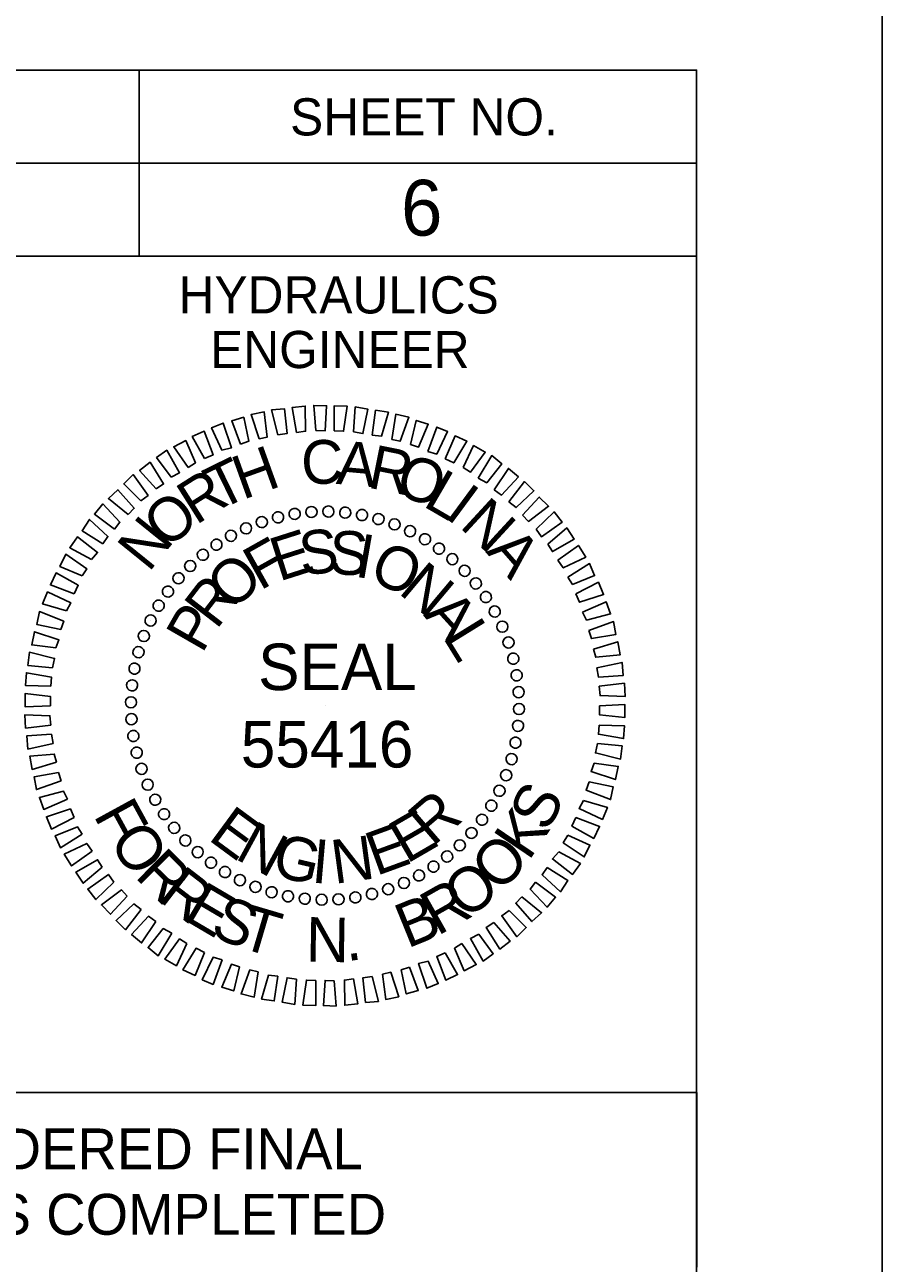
# Model space of a CAD drawing. Extents: x 573078 to 573131.9, y -55221.3 to -55195.5.
# Drawn here: x 573109.706 to 573112.014, y -55203.009 to -55199.677 of the extents above; entities that cross this region are included whole.
import ezdxf

# ---------------------------------------------------------------- set-up
doc = ezdxf.new("R2010")
doc.units = 0
for name, color, linetype in [('Prop Dimension', 7, 'Continuous'), ('Scratch_Level_0', 7, 'Continuous'), ('Scratch_Level_1', 7, 'Continuous'), ('Sheet Data Field CELL', 7, 'Continuous'), ('Sheet Plot Border Inside CELL', 7, 'Continuous'), ('Sheet Profile CELL', 7, 'Continuous'), ('Sheet Sticker Exception Certification CELL', 7, 'Continuous')]:
    doc.layers.add(name, color=color, linetype=linetype)

msp = doc.modelspace()

# ---------------------------------------------------------------- linework, layer by layer
at = {"layer": 'Prop Dimension'}
for p, q in [((573110.3871, -55201.0014), (573110.3871, -55201.0014)), ((573110.4329, -55200.9931), (573110.4329, -55200.9931)), ((573110.4776, -55200.9869), (573110.4776, -55200.9869)), ((573110.5234, -55200.9859), (573110.5234, -55200.9859)), ((573110.5692, -55200.9889), (573110.5692, -55200.9889)), ((573110.6141, -55200.9964), (573110.6141, -55200.9964)), ((573110.6579, -55201.0056), (573110.6579, -55201.0056)), ((573110.3017, -55201.0306), (573110.3017, -55201.0306)), ((573110.3434, -55201.0139), (573110.3434, -55201.0139)), ((573110.7016, -55201.0202), (573110.7016, -55201.0202)), ((573110.7433, -55201.0389), (573110.7433, -55201.0389)), ((573110.2214, -55201.0755), (573110.2214, -55201.0755)), ((573110.261, -55201.0514), (573110.261, -55201.0514)), ((573110.7838, -55201.0598), (573110.7838, -55201.0598)), ((573110.1851, -55201.1014), (573110.1851, -55201.1014)), ((573110.8213, -55201.0859), (573110.8213, -55201.0859)), ((573110.1506, -55201.1327), (573110.1506, -55201.1327)), ((573110.8578, -55201.1139), (573110.8578, -55201.1139)), ((573110.1194, -55201.1651), (573110.1194, -55201.1651)), ((573110.89, -55201.1452), (573110.89, -55201.1452)), ((573110.0914, -55201.2014), (573110.0914, -55201.2014)), ((573110.9212, -55201.1796), (573110.9212, -55201.1796)), ((573110.0652, -55201.2389), (573110.0652, -55201.2389)), ((573110.9474, -55201.216), (573110.9474, -55201.216)), ((573110.9712, -55201.2555), (573110.9712, -55201.2555)), ((573110.0444, -55201.2796), (573110.0444, -55201.2796)), ((573110.992, -55201.2963), (573110.992, -55201.2963)), ((573110.0256, -55201.3213), (573110.0256, -55201.3213)), ((573111.0087, -55201.3379), (573111.0087, -55201.3379)), ((573110.0111, -55201.365), (573110.0111, -55201.365)), ((573110.0018, -55201.4087), (573110.0018, -55201.4087)), ((573111.0212, -55201.3817), (573111.0212, -55201.3817)), ((573111.0295, -55201.4275), (573111.0295, -55201.4275)), ((573109.9944, -55201.4534), (573109.9944, -55201.4534)), ((573111.0358, -55201.4721), (573111.0358, -55201.4721)), ((573109.9914, -55201.4992), (573109.9914, -55201.4992)), ((573111.0369, -55201.518), (573111.0369, -55201.518)), ((573109.9923, -55201.545), (573109.9923, -55201.545)), ((573111.0337, -55201.5638), (573111.0337, -55201.5638)), ((573109.9986, -55201.5899), (573109.9986, -55201.5899)), ((573111.0265, -55201.6087), (573111.0265, -55201.6087)), ((573110.0069, -55201.6358), (573110.0069, -55201.6358)), ((573111.017, -55201.6524), (573111.017, -55201.6524)), ((573110.0194, -55201.6795), (573110.0194, -55201.6795)), ((573111.0025, -55201.6962), (573111.0025, -55201.6962)), ((573110.0361, -55201.7211), (573110.0361, -55201.7211)), ((573110.9837, -55201.7378), (573110.9837, -55201.7378)), ((573110.0569, -55201.7616), (573110.0569, -55201.7616)), ((573110.0809, -55201.8012), (573110.0809, -55201.8012)), ((573110.9629, -55201.7783), (573110.9629, -55201.7783)), ((573110.1069, -55201.8378), (573110.1069, -55201.8378)), ((573110.937, -55201.8158), (573110.937, -55201.8158)), ((573110.1381, -55201.872), (573110.1381, -55201.872)), ((573110.9087, -55201.8524), (573110.9087, -55201.8524)), ((573110.1705, -55201.9033), (573110.1705, -55201.9033)), ((573110.8775, -55201.8845), (573110.8775, -55201.8845)), ((573110.2068, -55201.9315), (573110.2068, -55201.9315)), ((573110.8067, -55201.9419), (573110.8067, -55201.9419)), ((573110.8432, -55201.9158), (573110.8432, -55201.9158)), ((573110.2443, -55201.9574), (573110.2443, -55201.9574)), ((573110.7671, -55201.9658), (573110.7671, -55201.9658)), ((573110.2851, -55201.9783), (573110.2851, -55201.9783)), ((573110.3267, -55201.997), (573110.3267, -55201.997)), ((573110.6849, -55202.0032), (573110.6849, -55202.0032)), ((573110.7266, -55201.9866), (573110.7266, -55201.9866)), ((573110.3705, -55202.0116), (573110.3705, -55202.0116)), ((573110.4142, -55202.0211), (573110.4142, -55202.0211)), ((573110.4589, -55202.0282), (573110.4589, -55202.0282)), ((573110.5047, -55202.0315), (573110.5047, -55202.0315)), ((573110.5505, -55202.0303), (573110.5505, -55202.0303)), ((573110.5954, -55202.0241), (573110.5954, -55202.0241)), ((573110.6412, -55202.0157), (573110.6412, -55202.0157))]:
    msp.add_line(p, q, dxfattribs=at)
for points in [[(573110.3871, -55200.7797), (573110.3705, -55200.7131), (573110.4047, -55200.7099), (573110.4121, -55200.7765)], [(573110.4371, -55200.7735), (573110.4255, -55200.7068), (573110.4609, -55200.7027), (573110.4621, -55200.7703)], [(573110.4892, -55200.7682), (573110.4838, -55200.7006), (573110.5183, -55200.7015), (573110.5142, -55200.7693)], [(573110.5392, -55200.7693), (573110.5392, -55200.7015), (573110.5734, -55200.7027), (573110.5641, -55200.7703)], [(573110.5912, -55200.7723), (573110.5954, -55200.7048), (573110.6296, -55200.711), (573110.6162, -55200.7765)], [(573110.2871, -55200.8047), (573110.2631, -55200.7423), (573110.2955, -55200.7328), (573110.3089, -55200.7973)], [(573110.3371, -55200.7911), (573110.3151, -55200.7256), (573110.3506, -55200.7182), (573110.3589, -55200.786)], [(573110.6412, -55200.7807), (573110.6505, -55200.714), (573110.6849, -55200.7193), (573110.6662, -55200.7839)], [(573110.6942, -55200.7922), (573110.7046, -55200.7244), (573110.74, -55200.7328), (573110.7162, -55200.7973)], [(573110.7442, -55200.8057), (573110.7599, -55200.7411), (573110.7921, -55200.7515), (573110.7662, -55200.8131)], [(573110.1902, -55200.8432), (573110.1569, -55200.7848), (573110.1893, -55200.7703), (573110.2131, -55200.8339)], [(573110.236, -55200.8214), (573110.2089, -55200.761), (573110.2402, -55200.7485), (573110.2621, -55200.8152)], [(573110.7912, -55200.8244), (573110.815, -55200.7589), (573110.8442, -55200.7714), (573110.815, -55200.8318)], [(573110.1455, -55200.8681), (573110.1069, -55200.8119), (573110.1393, -55200.7953), (573110.1652, -55200.8557)], [(573110.8379, -55200.8443), (573110.8641, -55200.7828), (573110.8962, -55200.7973), (573110.8608, -55200.8557)], [(573110.8858, -55200.8681), (573110.9141, -55200.8089), (573110.9453, -55200.8265), (573110.9057, -55200.8806)], [(573110.0997, -55200.8943), (573110.061, -55200.8411), (573110.0881, -55200.8214), (573110.1226, -55200.8818)], [(573110.9265, -55200.8964), (573110.9629, -55200.836), (573110.99, -55200.8577), (573110.9495, -55200.9089)], [(573110.0601, -55200.9255), (573110.0152, -55200.8756), (573110.0435, -55200.8536), (573110.0798, -55200.9119)], [(573110.9691, -55200.9276), (573111.0078, -55200.8702), (573111.0349, -55200.8931), (573110.989, -55200.9422)], [(573110.0185, -55200.9577), (573109.9726, -55200.9119), (573109.9976, -55200.8869), (573110.0381, -55200.9431)], [(573111.0087, -55200.9598), (573111.0515, -55200.9056), (573111.0765, -55200.9306), (573111.0286, -55200.9755)], [(573109.984, -55200.9943), (573109.931, -55200.9515), (573109.9569, -55200.9276), (573110.0006, -55200.9776)], [(573109.9477, -55201.0338), (573109.8935, -55200.9931), (573109.9164, -55200.966), (573109.9622, -55201.0151)], [(573111.0462, -55200.9964), (573111.0911, -55200.9473), (573111.1161, -55200.9723), (573111.0619, -55201.013)], [(573109.9164, -55201.0734), (573109.8602, -55201.038), (573109.8798, -55201.0077), (573109.9298, -55201.0535)], [(573111.0828, -55201.0338), (573111.1307, -55200.9869), (573111.1524, -55201.0151), (573111.0973, -55201.0547)], [(573111.114, -55201.0743), (573111.1649, -55201.0306), (573111.1848, -55201.0609), (573111.1265, -55201.0942)], [(573109.8852, -55201.1151), (573109.8269, -55201.0838), (573109.8477, -55201.0547), (573109.9018, -55201.0963)], [(573109.8602, -55201.1597), (573109.8007, -55201.1338), (573109.8164, -55201.1014), (573109.8727, -55201.1401)], [(573111.1411, -55201.1172), (573111.1961, -55201.0776), (573111.2161, -55201.1088), (573111.1556, -55201.138)], [(573111.1681, -55201.163), (573111.2265, -55201.1264), (573111.2399, -55201.1588), (573111.1806, -55201.1826)], [(573109.8394, -55201.2076), (573109.7748, -55201.1838), (573109.7903, -55201.1514), (573109.8498, -55201.1847)], [(573111.189, -55201.2076), (573111.2503, -55201.1764), (573111.264, -55201.2097), (573111.1994, -55201.2305)], [(573109.8185, -55201.2535), (573109.754, -55201.2347), (573109.7674, -55201.2025), (573109.8299, -55201.2317)], [(573111.2077, -55201.2567), (573111.2711, -55201.2296), (573111.2827, -55201.2618), (573111.2181, -55201.2784)], [(573109.8028, -55201.3034), (573109.7382, -55201.29), (573109.7456, -55201.2555), (573109.8111, -55201.2817)], [(573109.7894, -55201.3534), (573109.7248, -55201.3451), (573109.732, -55201.3097), (573109.7977, -55201.3317)], [(573111.2244, -55201.3067), (573111.291, -55201.2826), (573111.2973, -55201.3171), (573111.2316, -55201.3284)], [(573111.2369, -55201.3567), (573111.3024, -55201.3368), (573111.3086, -55201.3722), (573111.2431, -55201.3784)], [(573109.781, -55201.4067), (573109.7144, -55201.4004), (573109.7186, -55201.365), (573109.7861, -55201.3817)], [(573111.2461, -55201.4067), (573111.3139, -55201.3921), (573111.317, -55201.4275), (573111.2503, -55201.4316)], [(573109.7757, -55201.4566), (573109.7081, -55201.4546), (573109.7102, -55201.4201), (573109.7778, -55201.4316)], [(573109.7748, -55201.5087), (573109.707, -55201.5117), (573109.707, -55201.4763), (573109.7748, -55201.4837)], [(573111.2524, -55201.4566), (573111.3202, -55201.4483), (573111.3223, -55201.4837), (573111.2545, -55201.4816)], [(573111.2535, -55201.5087), (573111.3211, -55201.5055), (573111.3211, -55201.5409), (573111.2535, -55201.5337)], [(573109.7757, -55201.5608), (573109.7081, -55201.5691), (573109.7061, -55201.5337), (573109.7736, -55201.5358)], [(573111.2524, -55201.5608), (573111.3202, -55201.5629), (573111.3181, -55201.5971), (573111.2503, -55201.5858)], [(573109.782, -55201.6108), (573109.7144, -55201.6253), (573109.7111, -55201.5899), (573109.7778, -55201.5858)], [(573109.7914, -55201.6607), (573109.7257, -55201.6804), (573109.7195, -55201.645), (573109.7852, -55201.6388)], [(573111.2473, -55201.6108), (573111.3139, -55201.617), (573111.3098, -55201.6524), (573111.242, -55201.6358)], [(573111.239, -55201.6638), (573111.3035, -55201.6721), (573111.2961, -55201.7075), (573111.2306, -55201.6857)], [(573109.8039, -55201.7107), (573109.7373, -55201.7346), (573109.731, -55201.7003), (573109.7965, -55201.6888)], [(573109.8206, -55201.7607), (573109.757, -55201.7878), (573109.7456, -55201.7554), (573109.8102, -55201.7387)], [(573111.2253, -55201.7137), (573111.2899, -55201.7274), (573111.2827, -55201.7616), (573111.217, -55201.7357)], [(573111.2098, -55201.7637), (573111.2744, -55201.7825), (573111.2607, -55201.8149), (573111.1982, -55201.7857)], [(573109.8393, -55201.8096), (573109.7778, -55201.8408), (573109.7644, -55201.8075), (573109.8289, -55201.7866)], [(573111.189, -55201.8095), (573111.2535, -55201.8336), (573111.2378, -55201.8658), (573111.1786, -55201.8325)], [(573109.8602, -55201.8544), (573109.8019, -55201.8908), (573109.7882, -55201.8586), (573109.8477, -55201.8345)], [(573111.1681, -55201.8575), (573111.2274, -55201.8836), (573111.2119, -55201.9158), (573111.1556, -55201.8774)], [(573109.8873, -55201.9003), (573109.8319, -55201.9398), (573109.8123, -55201.9086), (573109.8727, -55201.8794)], [(573111.1432, -55201.9023), (573111.2015, -55201.9336), (573111.1806, -55201.9628), (573111.1265, -55201.9211)], [(573109.9143, -55201.9428), (573109.8632, -55201.9866), (573109.8435, -55201.9565), (573109.9018, -55201.9232)], [(573109.9456, -55201.9836), (573109.8977, -55202.0303), (573109.8757, -55202.0023), (573109.931, -55201.9628)], [(573111.1119, -55201.944), (573111.1681, -55201.9794), (573111.1482, -55202.0095), (573111.0983, -55201.9637)], [(573109.9819, -55202.0211), (573109.9372, -55202.0699), (573109.9122, -55202.0449), (573109.9664, -55202.0044)], [(573111.0807, -55201.9836), (573111.1348, -55202.0241), (573111.1119, -55202.0512), (573111.0661, -55202.0023)], [(573110.0194, -55202.0574), (573109.9768, -55202.1116), (573109.9518, -55202.0866), (573109.9997, -55202.0419)], [(573111.0441, -55202.0231), (573111.0973, -55202.0657), (573111.0712, -55202.0898), (573111.0274, -55202.0398)], [(573110.059, -55202.0898), (573110.0206, -55202.147), (573109.9935, -55202.124), (573110.0393, -55202.0752)], [(573111.0099, -55202.0595), (573111.0557, -55202.1053), (573111.0307, -55202.1303), (573110.99, -55202.0741)], [(573110.1018, -55202.121), (573110.0652, -55202.1814), (573110.0381, -55202.1595), (573110.0789, -55202.1085)], [(573110.9682, -55202.0919), (573111.0129, -55202.1419), (573110.9849, -55202.1636), (573110.9483, -55202.1053)], [(573110.1423, -55202.149), (573110.1143, -55202.2085), (573110.083, -55202.1907), (573110.1226, -55202.1365)], [(573110.9286, -55202.1231), (573110.967, -55202.1761), (573110.94, -55202.196), (573110.9057, -55202.1356)], [(573110.1902, -55202.1731), (573110.1643, -55202.2344), (573110.1319, -55202.2199), (573110.1673, -55202.1615)], [(573110.8379, -55202.174), (573110.8712, -55202.2323), (573110.8391, -55202.2469), (573110.815, -55202.1835)], [(573110.8828, -55202.149), (573110.9212, -55202.2053), (573110.8891, -55202.2219), (573110.8629, -55202.1615)], [(573110.2372, -55202.1928), (573110.2131, -55202.2585), (573110.1839, -55202.246), (573110.2131, -55202.1856)], [(573110.2839, -55202.2115), (573110.2684, -55202.2761), (573110.236, -55202.2657), (573110.2621, -55202.2044)], [(573110.7921, -55202.196), (573110.8192, -55202.2564), (573110.7879, -55202.2689), (573110.7662, -55202.2023)], [(573110.3339, -55202.2252), (573110.3235, -55202.2927), (573110.2881, -55202.2844), (573110.3121, -55202.2199)], [(573110.3871, -55202.2365), (573110.3776, -55202.3032), (573110.3434, -55202.2981), (573110.3621, -55202.2335)], [(573110.4371, -55202.2448), (573110.4329, -55202.3127), (573110.3985, -55202.3064), (573110.4121, -55202.2407)], [(573110.6412, -55202.2377), (573110.6579, -55202.3043), (573110.6234, -55202.3073), (573110.6162, -55202.2407)], [(573110.6912, -55202.2261), (573110.7129, -55202.2918), (573110.6775, -55202.299), (573110.6692, -55202.2314)], [(573110.7412, -55202.2127), (573110.765, -55202.2752), (573110.7329, -55202.2844), (573110.7192, -55202.2199)], [(573110.4892, -55202.2481), (573110.4892, -55202.3157), (573110.4547, -55202.3147), (573110.4642, -55202.2469)], [(573110.5392, -55202.249), (573110.5442, -55202.3168), (573110.51, -55202.3157), (573110.5142, -55202.2481)], [(573110.5912, -55202.2439), (573110.6026, -55202.3106), (573110.5672, -55202.3147), (573110.5662, -55202.2469)]]:
    msp.add_lwpolyline(points, close=True, dxfattribs=at)
for centre, major_axis in [((573110.4777, -55200.9876), (-0.001, 0.015)), ((573110.5233, -55200.9864), (0.0003, 0.015)), ((573110.5688, -55200.9892), (0.0016, 0.0149)), ((573110.3441, -55201.0147), (-0.0049, 0.0142)), ((573110.3878, -55201.0018), (-0.0036, 0.0146)), ((573110.4325, -55200.9927), (-0.0023, 0.0148)), ((573110.6138, -55200.9959), (0.0029, 0.0147)), ((573110.6582, -55201.0065), (0.0041, 0.0144)), ((573110.7014, -55201.021), (0.0054, 0.014)), ((573110.2609, -55201.0518), (-0.0073, 0.0131)), ((573110.3017, -55201.0315), (-0.0061, 0.0137)), ((573110.7432, -55201.0392), (0.0066, 0.0135)), ((573110.2221, -55201.0756), (-0.0084, 0.0124)), ((573110.7832, -55201.0609), (0.0077, 0.0129)), ((573110.8212, -55201.0861), (0.0088, 0.0121)), ((573110.1854, -55201.1027), (-0.0094, 0.0117)), ((573110.8569, -55201.1144), (0.0098, 0.0113)), ((573110.1513, -55201.1329), (-0.0104, 0.0108)), ((573110.8899, -55201.1458), (0.0108, 0.0104)), ((573110.1199, -55201.1659), (-0.0113, 0.0098)), ((573110.9201, -55201.1799), (0.0117, 0.0094)), ((573110.0916, -55201.2016), (-0.0121, 0.0088)), ((573110.9472, -55201.2165), (0.0124, 0.0084)), ((573110.0664, -55201.2396), (-0.0129, 0.0077)), ((573110.971, -55201.2554), (0.0131, 0.0073)), ((573110.0447, -55201.2797), (-0.0135, 0.0066)), ((573110.0265, -55201.3214), (-0.014, 0.0054)), ((573110.9914, -55201.2962), (0.0137, 0.0061)), ((573111.0081, -55201.3386), (0.0142, 0.0049)), ((573110.0121, -55201.3647), (-0.0144, 0.0041)), ((573111.021, -55201.3823), (0.0146, 0.0036)), ((573110.0014, -55201.409), (-0.0147, 0.0029)), ((573109.9947, -55201.454), (-0.0149, 0.0016)), ((573111.0301, -55201.4269), (0.0148, 0.0023)), ((573111.0353, -55201.4722), (0.015, 0.001)), ((573109.9919, -55201.4995), (-0.015, 0.0003)), ((573111.0364, -55201.5178), (0.015, -0.0003)), ((573109.9931, -55201.5451), (-0.015, -0.001)), ((573109.9983, -55201.5904), (-0.0148, -0.0023)), ((573111.0337, -55201.5632), (0.0149, -0.0016)), ((573111.0269, -55201.6083), (0.0147, -0.0029)), ((573110.0073, -55201.635), (-0.0146, -0.0036)), ((573111.0163, -55201.6526), (0.0144, -0.0041)), ((573110.0203, -55201.6787), (-0.0142, -0.0049)), ((573110.037, -55201.7211), (-0.0137, -0.0061)), ((573111.0018, -55201.6958), (0.014, -0.0054)), ((573110.9837, -55201.7376), (0.0135, -0.0066)), ((573110.0573, -55201.7619), (-0.0131, -0.0073)), ((573110.9619, -55201.7777), (0.0129, -0.0077)), ((573110.0811, -55201.8007), (-0.0124, -0.0084)), ((573110.9368, -55201.8157), (0.0121, -0.0088)), ((573110.1082, -55201.8374), (-0.0117, -0.0094)), ((573110.9084, -55201.8513), (0.0113, -0.0098)), ((573110.1384, -55201.8715), (-0.0108, -0.0104)), ((573110.877, -55201.8844), (0.0104, -0.0108)), ((573110.1715, -55201.9029), (-0.0098, -0.0113)), ((573110.8429, -55201.9146), (0.0094, -0.0117)), ((573110.2071, -55201.9312), (-0.0088, -0.0121)), ((573110.2451, -55201.9564), (-0.0077, -0.0129)), ((573110.8063, -55201.9417), (0.0084, -0.0124)), ((573110.2852, -55201.9781), (-0.0066, -0.0135)), ((573110.7266, -55201.9858), (0.0061, -0.0137)), ((573110.7674, -55201.9655), (0.0073, -0.0131)), ((573110.327, -55201.9963), (-0.0054, -0.014)), ((573110.3702, -55202.0108), (-0.0041, -0.0144)), ((573110.4145, -55202.0214), (-0.0029, -0.0147)), ((573110.5959, -55202.0246), (0.0023, -0.0148)), ((573110.6405, -55202.0155), (0.0036, -0.0146)), ((573110.6842, -55202.0025), (0.0049, -0.0142)), ((573110.4596, -55202.0281), (-0.0016, -0.0149)), ((573110.5051, -55202.0309), (-0.0003, -0.015)), ((573110.5506, -55202.0297), (0.001, -0.015))]:
    msp.add_ellipse(centre, major_axis=major_axis, ratio=0.999708, dxfattribs=at)
at = {"layer": 'Scratch_Level_0'}
msp.add_line((573110.5142, -55201.5087), (573110.5142, -55201.5087), dxfattribs=at)
at = {"layer": 'Scratch_Level_1'}
msp.add_line((573110.5142, -55201.5087), (573110.5142, -55201.5087), dxfattribs=at)
at = {"layer": 'Sheet Plot Border Inside CELL'}
msp.add_lwpolyline([(573112.0142, -55199.2984), (573078.0142, -55199.2984), (573078.0142, -55221.2984), (573112.0142, -55221.2984)], close=True, dxfattribs=at)
at = {"layer": 'Sheet Profile CELL'}
for p, q in [((573110.0142, -55199.7994), (573110.0142, -55200.2994)), ((573107.5142, -55200.0494), (573111.5142, -55200.0494))]:
    msp.add_line(p, q, dxfattribs=at)
for points in [[(573111.5142, -55199.7984), (573081.5142, -55199.7984), (573081.5142, -55220.7984), (573111.5142, -55220.7984)], [(573107.5142, -55199.7984), (573111.5142, -55199.7984), (573111.5142, -55200.2994), (573107.5142, -55200.2994)], [(573109.5142, -55200.2994), (573111.5142, -55200.2994), (573111.5142, -55202.5494), (573109.5142, -55202.5494)]]:
    msp.add_lwpolyline(points, close=True, dxfattribs=at)
at = {"layer": 'Sheet Sticker Exception Certification CELL'}
for p, q in [((573107.5142, -55202.5494), (573111.5149, -55202.5494)), ((573111.5149, -55202.5494), (573111.5149, -55203.0194))]:
    msp.add_line(p, q, dxfattribs=at)

# ---------------------------------------------------------------- texts
at = {"layer": 'Prop Dimension'}
for s, height, rotation, p in [('C', 0.1177, 1.0718, (573110.4508, -55200.9128)), ('A', 0.1177, 354.8222, (573110.5424, -55200.9117)), ('R', 0.1177, 348.5725, (573110.6257, -55200.9211)), ('T', 0.1177, 26.0703, (573110.2291, -55200.9846)), ('H', 0.1177, 19.8207, (573110.2925, -55200.9554)), ('O', 0.1177, 342.3229, (573110.6986, -55200.9399)), ('L', 0.1177, 329.8237, (573110.7747, -55200.97)), ('R', 0.1177, 32.3199, (573110.1666, -55201.0241)), ('I', 0.1177, 323.5741, (573110.8331, -55201.0003)), ('O', 0.1177, 38.5695, (573110.0863, -55201.0898)), ('N', 0.1177, 317.3244, (573110.8736, -55201.0274)), ('N', 0.1177, 51.0688, (573110.0395, -55201.1523)), ('E', 0.1177, 17.6709, (573110.3904, -55201.1752)), ('S', 0.1177, 6.1833, (573110.4508, -55201.1586)), ('S', 0.1177, 358.4778, (573110.5248, -55201.1553)), ('F', 0.1177, 29.3, (573110.3394, -55201.2002)), ('I', 0.1177, 350.0931, (573110.5915, -55201.1607)), ('O', 0.1177, 335.3611, (573110.6278, -55201.1678)), ('A', 0.1177, 311.0748, (573110.9455, -55201.0949)), ('O', 0.1177, 43.5875, (573110.2654, -55201.2565)), ('N', 0.1177, 319.95, (573110.709, -55201.2044)), ('R', 0.1177, 52.4166, (573110.2217, -55201.3065)), ('P', 0.1177, 60.1222, (573110.1832, -55201.371)), ('A', 0.1177, 312.2445, (573110.7777, -55201.2657)), ('L', 0.1177, 301.6752, (573110.8298, -55201.324)), ('SEAL', 0.12497, 360, (573110.3341, -55201.4668)), ('55416', 0.12497, 360, (573110.2874, -55201.6751)), ('S', 0.12, 63.6332, (573111.1135, -55201.8519)), ('F', 0.12, 298.6676, (573109.8895, -55201.8032)), ('R', 0.1177, 40.7353, (573110.8039, -55201.8896)), ('E', 0.1177, 323.6798, (573110.1967, -55201.8676)), ('E', 0.1177, 30.1214, (573110.734, -55201.9354)), ('K', 0.12, 55.9775, (573111.0624, -55201.9287)), ('O', 0.12, 305.5335, (573109.9292, -55201.8757)), ('N', 0.1177, 331.3854, (573110.2686, -55201.9188)), ('E', 0.1177, 20.0411, (573110.6519, -55201.9676)), ('G', 0.1177, 346.7965, (573110.3674, -55201.9646)), ('I', 0.1177, 355.0405, (573110.4757, -55201.9843)), ('N', 0.1177, 7.7341, (573110.5394, -55201.9884)), ('O', 0.12, 46.28, (573110.9838, -55202.015)), ('R', 0.12, 315.231, (573109.9993, -55201.969)), ('R', 0.12, 322.3858, (573110.0607, -55202.0296)), ('O', 0.12, 36.5825, (573110.8918, -55202.0869)), ('E', 0.12, 329.5406, (573110.1291, -55202.082)), ('R', 0.12, 29.4277, (573110.8169, -55202.1294)), ('S', 0.12, 336.4643, (573110.201, -55202.1242)), ('B', 0.12, 22.1381, (573110.7357, -55202.1628)), ('T', 0.12, 343.5228, (573110.279, -55202.1581)), ('N', 0.12, 359.1037, (573110.4621, -55202.1974)), ('.', 0.12, 8.2811, (573110.5726, -55202.1968))]:
    msp.add_text(s, height=height, rotation=rotation, dxfattribs=at).set_placement(p)
at = {"layer": 'Sheet Data Field CELL'}
msp.add_text('6', height=0.15, dxfattribs=at).set_placement((573110.7188, -55200.2439))
at = {"layer": 'Sheet Profile CELL'}
for s, p in [('SHEET NO.', (573110.4202, -55199.9744)), ('HYDRAULICS', (573110.12, -55200.4534)), ('ENGINEER', (573110.205, -55200.6004))]:
    msp.add_text(s, height=0.1, dxfattribs=at).set_placement(p)
at = {"layer": 'Sheet Sticker Exception Certification CELL'}
for s, p in [('DOCUMENT NOT CONSIDERED FINAL', (573107.9356, -55202.7563)), ('UNLESS ALL SIGNATURES COMPLETED', (573107.8342, -55202.9323))]:
    msp.add_text(s, height=0.11, dxfattribs=at).set_placement(p)

doc.saveas('drawing.dxf')
